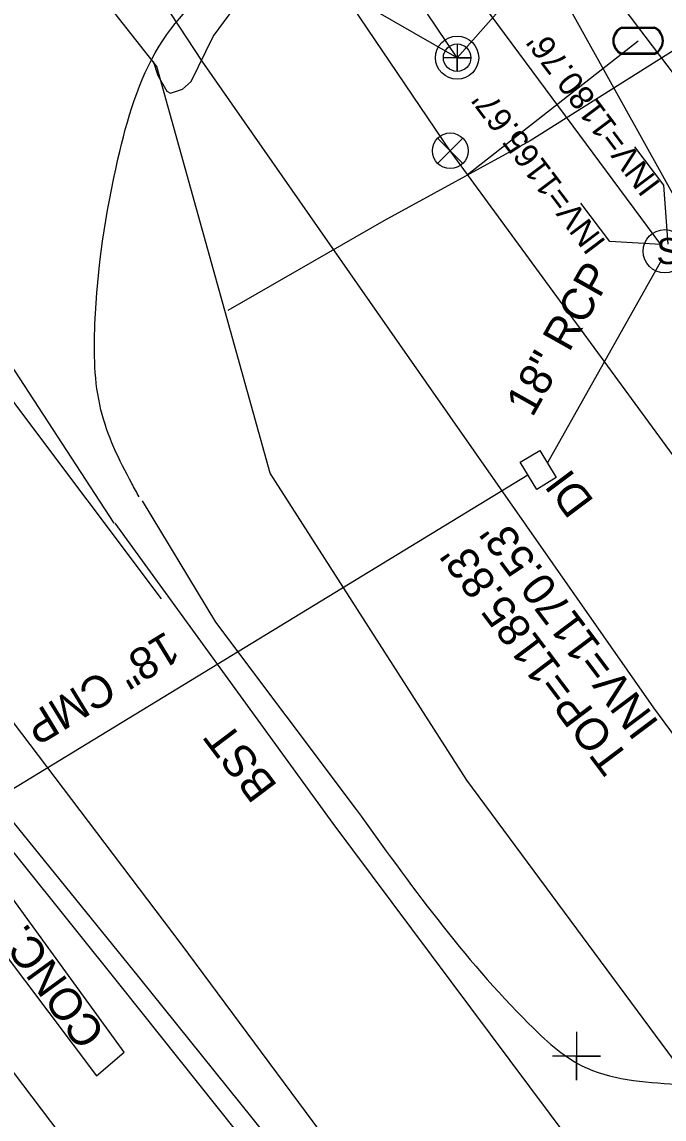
# Model space of a CAD drawing. Extents: x 1262092 to 1264624, y 774970 to 778314.
# Drawn here: x 1263623.1 to 1263703.3, y 776218.9 to 776355.9 of the extents above; entities that cross this region are included whole.
import ezdxf

# ---------------------------------------------------------------- set-up
doc = ezdxf.new("R2010")
doc.units = 0
for name, color, linetype in [('Exist DTM Spot Elevation CELL', 7, 'Continuous'), ('Exist Right of Way Line', 7, 'Continuous'), ('Exist Roads EOP', 7, 'Continuous'), ('Exist Roads EOT', 7, 'Continuous'), ('Exist Structure Minor Drop Inlet', 7, 'Continuous'), ('Exist Structure Minor Drop Inlet Text', 7, 'Continuous'), ('Exist Structure Minor Drop Inlet Top Elevation', 7, 'Continuous'), ('Exist Structure Minor Paved Ditch or Gutter', 7, 'Continuous'), ('Exist Structure Minor Paved Ditch or Gutter Text', 7, 'Continuous'), ('Exist Structure Minor Pipes CMP 18 Inch', 7, 'Continuous'), ('Exist Structure Minor Pipes CMP 18 Inch Invert', 7, 'Continuous'), ('Exist Structure Minor Pipes CMP 18 Inch Text', 7, 'Continuous'), ('Exist Structure Minor Pipes HDPE 15 Inch Invert', 7, 'Continuous'), ('Exist Structure Minor Pipes HDPE 15 Inch Leader', 7, 'Continuous'), ('Exist Structure Minor Pipes RCP 18 Inch Text', 7, 'Continuous'), ('Exist Structure Minor Pipes RCP 24 Inch Invert', 7, 'Continuous'), ('Exist Structure Minor Pipes RCP 24 Inch Leader', 7, 'Continuous'), ('Exist Structure Minor Pipes RCP 30 Inch', 7, 'Continuous'), ('Exist Structure Minor Storm Sewer Manhole CELL', 7, 'Continuous'), ('Exist Utilities Gas UG Line SUE LOS B', 7, 'Continuous'), ('Exist Utilities Sanitary Sewer Manhole CELL', 7, 'Continuous'), ('Exist Utilities Sanitary Sewer Manhole Leader', 7, 'Continuous'), ('Exist Utilities Sanitary Sewer UG Line', 7, 'Continuous'), ('Exist Utilities Water Meter CELL', 7, 'Continuous'), ('Exist Utilities Water UG Line SUE LOS B', 7, 'Continuous'), ('Exist Utilities Water Valve CELL', 7, 'Continuous'), ('Prop Horizontal Alignment', 7, 'Continuous'), ('Prop Superelevation Label', 7, 'Continuous')]:
    doc.layers.add(name, color=color, linetype=linetype)

# ---------------------------------------------------------------- blocks, each defined once
blk = doc.blocks.new('EXIST UTILITIES SANITARY SEWER MANHOLE')
at = {"layer": 'Exist Utilities Sanitary Sewer Manhole CELL'}
blk.add_lwpolyline([(0, 0.03425), (0, -0.03425), (0, 0), (0.03425, 0), (-0.03425, 0)], dxfattribs=at)
for radius in [0.05389, 0.03425]:
    blk.add_circle((0, 0), radius, dxfattribs=at)
blk = doc.blocks.new('EXIST UTILITIES WATER VALVE')
at = {"layer": 'Exist Utilities Water Valve CELL'}
blk.add_lwpolyline([(0.0315, 0.0315), (-0.0315, -0.0315), (0, 0), (0.0315, -0.0315), (-0.0315, 0.0315)], dxfattribs=at)
blk.add_circle((0, 0), 0.0445, dxfattribs=at)
blk = doc.blocks.new('EXIST UTILITIES WATER METER')
at = {"layer": 'Exist Utilities Water Meter CELL'}
blk.add_line((0, 0), (0, 0), dxfattribs=at)
for points in [[(-0.0408, 0.034), (0.0408, 0.034)], [(-0.0408, 0.0312), (0.0408, 0.0312)], [(0.0408, -0.0312), (-0.0413, -0.0312)], [(0.0408, -0.034), (-0.0413, -0.034)]]:
    blk.add_lwpolyline(points, dxfattribs=at)
for centre, radius, start, end in [((-0.0261, -0.0001), 0.0371, 113.178, 245.9794), ((-0.0259, -0.0001), 0.0347, 115.3009, 243.7824), ((0.0259, 0), 0.0371, 293.6483, 66.3084), ((0.0261, 0), 0.0345, 295.1272, 64.8728)]:
    blk.add_arc(centre, radius, start, end, dxfattribs=at)
blk = doc.blocks.new('EXIST DTM SPOT ELEVATION')
at = {"layer": 'Exist DTM Spot Elevation CELL'}
blk.add_lwpolyline([(0, 0.06), (0, -0.06), (0, 0), (0.06, 0), (-0.06, 0)], dxfattribs=at)
blk = doc.blocks.new('EXIST STRUCTURE MINOR STORM SEWER MANHOLE')
at = {"layer": 'Exist Structure Minor Storm Sewer Manhole CELL'}
blk.add_circle((0, 0), 0.0539, dxfattribs=at)
blk.add_text('S', height=0.065, dxfattribs=at).set_placement((-0.0206, -0.032))

msp = doc.modelspace()

# ---------------------------------------------------------------- linework, layer by layer
at = {"layer": 'Exist Right of Way Line'}
msp.add_line((1263590.4, 776500.74), (1264585.76, 775179.25), dxfattribs=at)
at = {"layer": 'Exist Roads EOP'}
for points in [[(1263413.16, 776522.85), (1263445.57, 776480.47), (1263475.98, 776441.07), (1263505.37, 776401.98), (1263533.63, 776365.61), (1263560.86, 776329.4), (1263590.43, 776291.68), (1263635.67, 776235.21)], [(1263549.45, 776320.86), (1263578.64, 776283.05), (1263606.19, 776245.65), (1263633.43, 776209.7), (1263659.27, 776175.1), (1263687.76, 776137.36), (1263716.42, 776099.4), (1263744.97, 776061.42), (1263771.41, 776026.48), (1263799.02, 775989.75), (1263826.98, 775952.54), (1263853.49, 775916.6), (1263882.15, 775878.99), (1263908.85, 775843.6), (1263935.68, 775807.66), (1263961.78, 775772.43), (1263989.03, 775736.19), (1264015.83, 775700.49)], [(1263638.14, 776296.07), (1263647.3, 776280.93), (1263664.84, 776257.58)], [(1263635.67, 776235.21), (1263664.15, 776199.52), (1263694.11, 776162.22), (1263723.19, 776125.55), (1263739.53, 776104.93), (1263766.81, 776069.09), (1263796.15, 776030.19), (1263824.31, 775992.83), (1263865.34, 775938.5), (1263893.23, 775901.06), (1263922.52, 775862.2), (1263949.95, 775825.28), (1263977.99, 775788.17), (1264005.13, 775752.44), (1264032.99, 775715.55), (1264060.75, 775678.62), (1264088.38, 775641.53), (1264133.95, 775582.22)]]:
    msp.add_lwpolyline(points, dxfattribs=at)
for points in [[(1263637.76, 776296.57), (1263636.84, 776298.25), (1263632.99, 776307.46), (1263632.24, 776318.16), (1263635.12, 776338.75), (1263640.25, 776352.82), (1263649.72, 776363.33)], [(1263664.84, 776257.58), (1263686.4, 776230.8), (1263692.99, 776225.58), (1263704.8, 776223.28), (1263715.24, 776223.46), (1263726.55, 776227.96), (1263753.47, 776247.69)]]:
    msp.add_spline(points, degree=3, dxfattribs=at)
at = {"layer": 'Exist Roads EOT'}
for points in [[(1263446.47, 776542.66), (1263480.06, 776497.71), (1263508.92, 776459.34), (1263541, 776416.36), (1263573.06, 776373.75), (1263603.22, 776333.46), (1263640.52, 776283.84)], [(1263482.8, 776515.47), (1263509.89, 776477.8), (1263537.29, 776440.12), (1263563.31, 776402.14), (1263589.36, 776362.47), (1263614.5, 776324.1), (1263634.59, 776293.28)], [(1263634.71, 776293.29), (1263661.92, 776255.81), (1263688.91, 776219.66), (1263718.75, 776179.84), (1263747.13, 776142.27), (1263762.04, 776122.53), (1263790.78, 776084.44), (1263819.18, 776046.81), (1263847.86, 776008.49), (1263857.04, 775996.7)], [(1263613.54, 776279.59), (1263642.97, 776240.78), (1263670.4, 776203.78), (1263698.68, 776166.01), (1263727.22, 776128.29), (1263740.58, 776110.22)], [(1263607.01, 776274.46), (1263637.64, 776236.73), (1263666.33, 776201.02), (1263696.03, 776164.2), (1263725.98, 776127.31), (1263742.41, 776107.39), (1263769.94, 776071.32), (1263798.94, 776032.46), (1263827.52, 775994.61), (1263868.02, 775940.4), (1263896.06, 775903.09), (1263925.16, 775864.32), (1263952.94, 775827.49), (1263980.85, 775790.42), (1264008.12, 775754.34), (1264035.58, 775717.72), (1264063.46, 775680.83), (1264091.3, 775643.74), (1264117.07, 775609.33), (1264137.68, 775581.96)]]:
    msp.add_lwpolyline(points, dxfattribs=at)
at = {"layer": 'Exist Structure Minor Drop Inlet'}
msp.add_lwpolyline([(1263685.32, 776300.91), (1263687.74, 776302.39), (1263689.81, 776299), (1263687.38, 776297.52), (1263685.32, 776300.91)], dxfattribs=at)
at = {"layer": 'Exist Structure Minor Paved Ditch or Gutter'}
msp.add_lwpolyline([(1263632.42, 776224.31), (1263635.88, 776227.28), (1263595.16, 776283.32), (1263590.76, 776279.64), (1263632.42, 776224.31)], dxfattribs=at)
at = {"layer": 'Exist Structure Minor Pipes CMP 18 Inch'}
for p, q in [((1263688.75, 776300.86), (1263703.03, 776326.24)), ((1263613.68, 776255.06), (1263686.24, 776299.34))]:
    msp.add_line(p, q, dxfattribs=at)
at = {"layer": 'Exist Structure Minor Pipes HDPE 15 Inch Leader'}
msp.add_lwpolyline([(1263703.78, 776328.14), (1263703.24, 776335.48), (1263699.63, 776340.27)], dxfattribs=at)
at = {"layer": 'Exist Structure Minor Pipes RCP 24 Inch Leader'}
msp.add_lwpolyline([(1263702.86, 776328.08), (1263696.47, 776328.47), (1263692.86, 776333.26)], dxfattribs=at)
at = {"layer": 'Exist Structure Minor Pipes RCP 30 Inch'}
msp.add_line((1263702.86, 776328.08), (1263630.66, 776425.67), dxfattribs=at)
at = {"layer": 'Exist Utilities Gas UG Line SUE LOS B'}
for points in [[(1263999.19, 775839.39), (1263985.7, 775869), (1263961.35, 775898.49), (1263933.55, 775929.39), (1263903.92, 775964.01), (1263874.9, 776001.17), (1263844.84, 776038.67), (1263814.72, 776080.57), (1263786.93, 776117.1), (1263768.77, 776141.15), (1263740.07, 776178.28), (1263709.03, 776220.12), (1263678.63, 776261.22), (1263654.09, 776299.54), (1263639.97, 776350.31), (1263613.73, 776383.62), (1263581.55, 776427.09), (1263558.06, 776458.02), (1263528.1, 776503.73), (1263523.32, 776512.13)], [(1263762.74, 776390.22), (1263730.67, 776368.85), (1263686.53, 776341.02), (1263668.27, 776331.04), (1263648.83, 776319.84)], [(1263762.74, 776390.22), (1263730.67, 776368.85), (1263686.53, 776341.02), (1263668.27, 776331.04), (1263648.83, 776319.84)]]:
    msp.add_lwpolyline(points, dxfattribs=at)
at = {"layer": 'Exist Utilities Sanitary Sewer Manhole Leader'}
msp.add_lwpolyline([(1263677.43, 776351.4), (1263650.61, 776366.8), (1263647, 776371.59)], dxfattribs=at)
at = {"layer": 'Exist Utilities Sanitary Sewer UG Line'}
msp.add_line((1263677.43, 776351.4), (1263523.17, 776581.72), dxfattribs=at)
msp.add_lwpolyline([(1263737.88, 776274.15), (1263688.17, 776363.52), (1263677.43, 776351.4)], dxfattribs=at)
at = {"layer": 'Exist Utilities Water UG Line SUE LOS B'}
msp.add_line((1263678.73, 776336.83), (1263700.02, 776353.51), dxfattribs=at)
for points in [[(1263769.27, 776215.45), (1263763.84, 776222.23), (1263735.1, 776261.82), (1263710.78, 776293), (1263676.58, 776339.78), (1263655.95, 776370.3), (1263625.27, 776411.83), (1263600.5, 776445.06), (1263569.27, 776485), (1263544.4, 776518.91), (1263522.5, 776549.75)], [(1263947.84, 775937.63), (1263921.48, 775975.65), (1263891.78, 776015.72), (1263866.35, 776051.64), (1263834.78, 776093.68), (1263806.91, 776131.82), (1263785.84, 776159.4), (1263762.42, 776192.1), (1263728.85, 776233.86), (1263701.99, 776270.27), (1263670.29, 776315.62), (1263645.61, 776350.98), (1263620.38, 776389.35), (1263590.58, 776434.56), (1263568.12, 776469.9), (1263541.87, 776510.41), (1263521.01, 776540.13)]]:
    msp.add_lwpolyline(points, dxfattribs=at)
at = {"layer": 'Prop Superelevation Label'}
msp.add_lwpolyline([(1263639.49, 776350.95), (1263640.11, 776349.18), (1263641.22, 776347.23), (1263641.68, 776346.97), (1263643.15, 776347.47), (1263644.26, 776348.43), (1263647.01, 776354.06), (1263649.69, 776357.7), (1263651.72, 776360.6), (1263650.74, 776362.47), (1263650, 776363.54)], dxfattribs=at)

# ---------------------------------------------------------------- block references
at = {"layer": 'Exist DTM Spot Elevation CELL', "xscale": 50, "yscale": 50}
msp.add_blockref('EXIST DTM SPOT ELEVATION', (1263692.33, 776226.79), dxfattribs=at)
at = {"layer": 'Exist Structure Minor Storm Sewer Manhole CELL', "xscale": 50, "yscale": 50}
msp.add_blockref('EXIST STRUCTURE MINOR STORM SEWER MANHOLE', (1263703.34, 776327.24), dxfattribs=at)
at = {"layer": 'Exist Utilities Sanitary Sewer Manhole CELL', "xscale": 50, "yscale": 50}
msp.add_blockref('EXIST UTILITIES SANITARY SEWER MANHOLE', (1263677.43, 776351.4), dxfattribs=at)
msp.add_blockref('EXIST UTILITIES SANITARY SEWER MANHOLE', (1263677.43, 776351.4), dxfattribs=at)
at = {"layer": 'Exist Utilities Water Meter CELL', "xscale": 50, "yscale": 50}
msp.add_blockref('EXIST UTILITIES WATER METER', (1263700.02, 776353.51), dxfattribs=at)
at = {"layer": 'Exist Utilities Water Valve CELL', "xscale": 50, "yscale": 50}
msp.add_blockref('EXIST UTILITIES WATER VALVE', (1263676.58, 776339.78), dxfattribs=at)

# ---------------------------------------------------------------- texts
at = {"layer": 'Exist Structure Minor Drop Inlet Text'}
msp.add_text('DI', height=4, rotation=126.9874, dxfattribs=at).set_placement((1263694.62, 776296.04))
at = {"layer": 'Exist Structure Minor Drop Inlet Top Elevation'}
msp.add_text("TOP=1185.83'", height=4, rotation=126.9874, dxfattribs=at).set_placement((1263699.06, 776263.92))
at = {"layer": 'Exist Structure Minor Paved Ditch or Gutter Text'}
msp.add_text('CONC.', height=4, rotation=126.0083, dxfattribs=at).set_placement((1263633.69, 776229.65))
at = {"layer": 'Exist Structure Minor Pipes CMP 18 Inch Invert'}
msp.add_text("INV=1170.53'", height=4, rotation=126.9874, dxfattribs=at).set_placement((1263702.74, 776268.34))
at = {"layer": 'Exist Structure Minor Pipes CMP 18 Inch Text'}
msp.add_text('18" CMP', height=4, rotation=211.3995, dxfattribs=at).set_placement((1263641.15, 776279.9))
at = {"layer": 'Exist Structure Minor Pipes HDPE 15 Inch Invert'}
msp.add_text("INV=1180.76'", height=3, rotation=126.9874, dxfattribs=at).set_placement((1263702.94, 776335.62))
at = {"layer": 'Exist Structure Minor Pipes RCP 18 Inch Text'}
msp.add_text('18" RCP', height=4, rotation=60.6217, dxfattribs=at).set_placement((1263686.82, 776306.4))
at = {"layer": 'Exist Structure Minor Pipes RCP 24 Inch Invert'}
msp.add_text("INV=1165.67'", height=3, rotation=126.9874, dxfattribs=at).set_placement((1263696.1, 776328.37))
at = {"layer": 'Prop Horizontal Alignment'}
msp.add_text('BST', height=4, rotation=126.9874, dxfattribs=at).set_placement((1263655.12, 776260.49))
msp.add_text('BST', height=4, rotation=126.9874, dxfattribs=at).set_placement((1263655.12, 776260.49))

doc.saveas('drawing.dxf')
